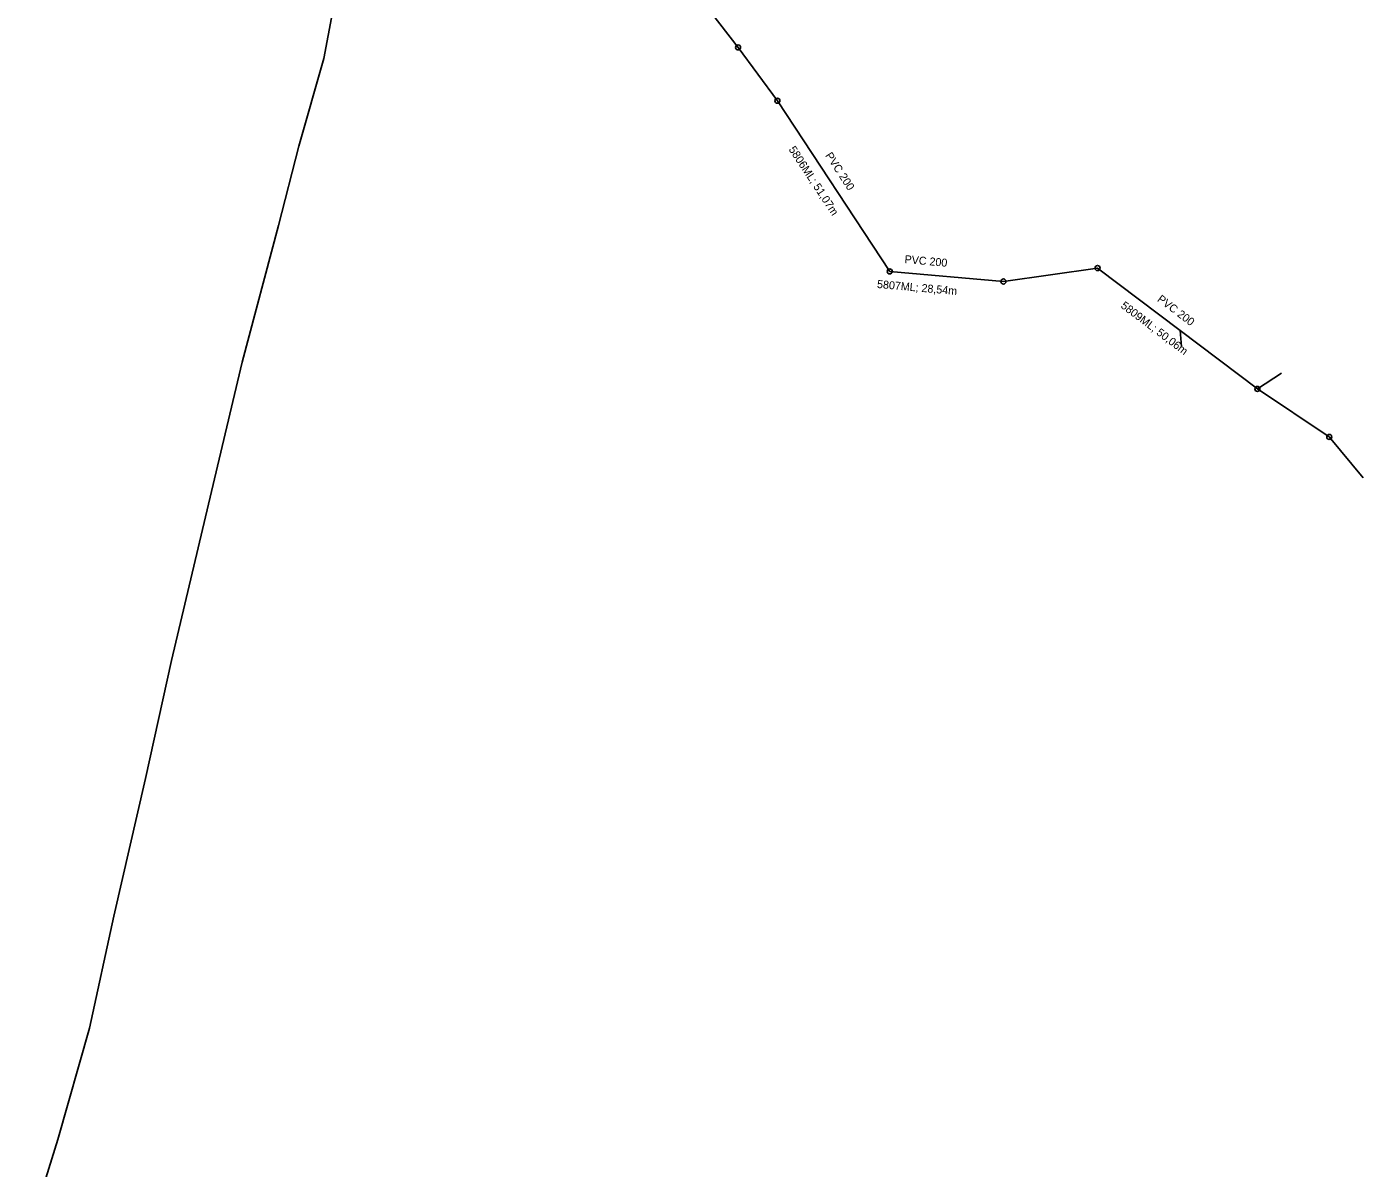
# Model space of a CAD drawing. Extents: x -867696 to -865033, y -1042522 to -1039817.
# Drawn here: x -865367.1 to -865033, y -1041184.7 to -1040899.3 of the extents above; entities that cross this region are included whole.
import ezdxf

# ---------------------------------------------------------------- set-up
doc = ezdxf.new("R2010")
doc.units = 0
for name, color, linetype in [('KN - popis material', 7, 'Continuous'), ('KN - popis usek delka', 7, 'Continuous'), ('KN - pripojka', 7, 'Continuous'), ('KN - sachta komora', 7, 'Continuous'), ('KN - splaskova', 7, 'Continuous'), ('Level 1', 7, 'Continuous'), ('V - rozvadeci', 7, 'Continuous')]:
    doc.layers.add(name, color=color, linetype=linetype)

# ---------------------------------------------------------------- blocks, each defined once
blk = doc.blocks.new('100.M')
at = {"layer": 'Level 1'}
blk.add_circle((0, 0), 1.27, dxfattribs=at)

msp = doc.modelspace()

# ---------------------------------------------------------------- linework, layer by layer
at = {"layer": 'KN - pripojka'}
for points in [[(-865078.696, -1040975.278), (-865078.43, -1040979.28)], [(-865059.44, -1040989.85), (-865053.42, -1040985.92)], [(-865041.47, -1041001.86), (-865032.96, -1041012.06)]]:
    msp.add_lwpolyline(points, dxfattribs=at)
at = {"layer": 'KN - splaskova'}
for points in [[(-865189.246, -1040904.495), (-865215.862, -1040870.025)], [(-865179.42, -1040917.82), (-865189.246, -1040904.495)], [(-865179.42, -1040917.82), (-865151.35, -1040960.48)], [(-865122.92, -1040963.01), (-865099.36, -1040959.64)], [(-865099.36, -1040959.64), (-865078.696, -1040975.278), (-865059.44, -1040989.85)], [(-865151.35, -1040960.48), (-865122.92, -1040963.01)], [(-865059.44, -1040989.85), (-865041.47, -1041001.86)]]:
    msp.add_lwpolyline(points, dxfattribs=at)
at = {"layer": 'V - rozvadeci'}
msp.add_lwpolyline([(-865218.08, -1040789.44), (-865221.302, -1040790.746), (-865242.12, -1040799.77), (-865254.24, -1040805.3), (-865256.14, -1040810.11), (-865249.4, -1040837.49), (-865253.1, -1040842.97), (-865287.39, -1040876.73), (-865288.71, -1040885.55), (-865292.82, -1040907.3), (-865299.09, -1040929.21), (-865304.16, -1040948.97), (-865313.2, -1040983.18), (-865320.84, -1041015.47), (-865330.84, -1041057.71), (-865337.42, -1041087.21), (-865345.33, -1041121.67), (-865351.4, -1041149.61), (-865359.29, -1041177.45), (-865364.92, -1041195.75), (-865366.18, -1041200.61), (-865367.07, -1041205.82), (-865365.16, -1041210.96), (-865359.01, -1041217.82)], dxfattribs=at)

# ---------------------------------------------------------------- block references
at = {"layer": 'KN - sachta komora'}
for p, xscale, yscale, rotation in [((-865189.246, -1040904.495), 0.5000000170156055, 0.5000000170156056, -51.999999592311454), ((-865179.42, -1040917.82), 0.5000000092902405, 0.5000000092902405, -54.99999976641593), ((-865151.35, -1040960.48), 0.4999999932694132, 0.4999999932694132, -30.00000044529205), ((-865099.36, -1040959.64), 0.5004924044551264, 0.5004924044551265, -14.224326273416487), ((-865122.92, -1040963.01), 0.500000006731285, 0.5000000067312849, 1.9999999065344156), ((-865059.44, -1040989.85), 0.5000000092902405, 0.5000000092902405, -35.000000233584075), ((-865041.47, -1041001.86), 0.4999999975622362, 0.4999999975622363, -33.000001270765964)]:
    msp.add_blockref('100.M', p, dxfattribs=dict(at, xscale=xscale, yscale=yscale, rotation=rotation))

# ---------------------------------------------------------------- texts
at = {"layer": 'KN - popis material'}
for rotation, p in [(303.34, (-865167.54, -1040931.507)), (354.91, (-865147.692, -1040958.396)), (322.88, (-865084.626, -1040967.78))]:
    msp.add_text('PVC 200', height=2, rotation=rotation, dxfattribs=at).set_placement(p)
at = {"layer": 'KN - popis usek delka'}
for s, rotation, p in [('5806ML; 51,07m', 303.34, (-865176.684, -1040929.982)), ('5807ML; 28,54m', 354.91, (-865154.569, -1040964.61)), ('5809ML; 50,06m', 322.88, (-865093.752, -1040969.401))]:
    msp.add_text(s, height=1.99999, rotation=rotation, dxfattribs=at).set_placement(p)

doc.saveas('drawing.dxf')
